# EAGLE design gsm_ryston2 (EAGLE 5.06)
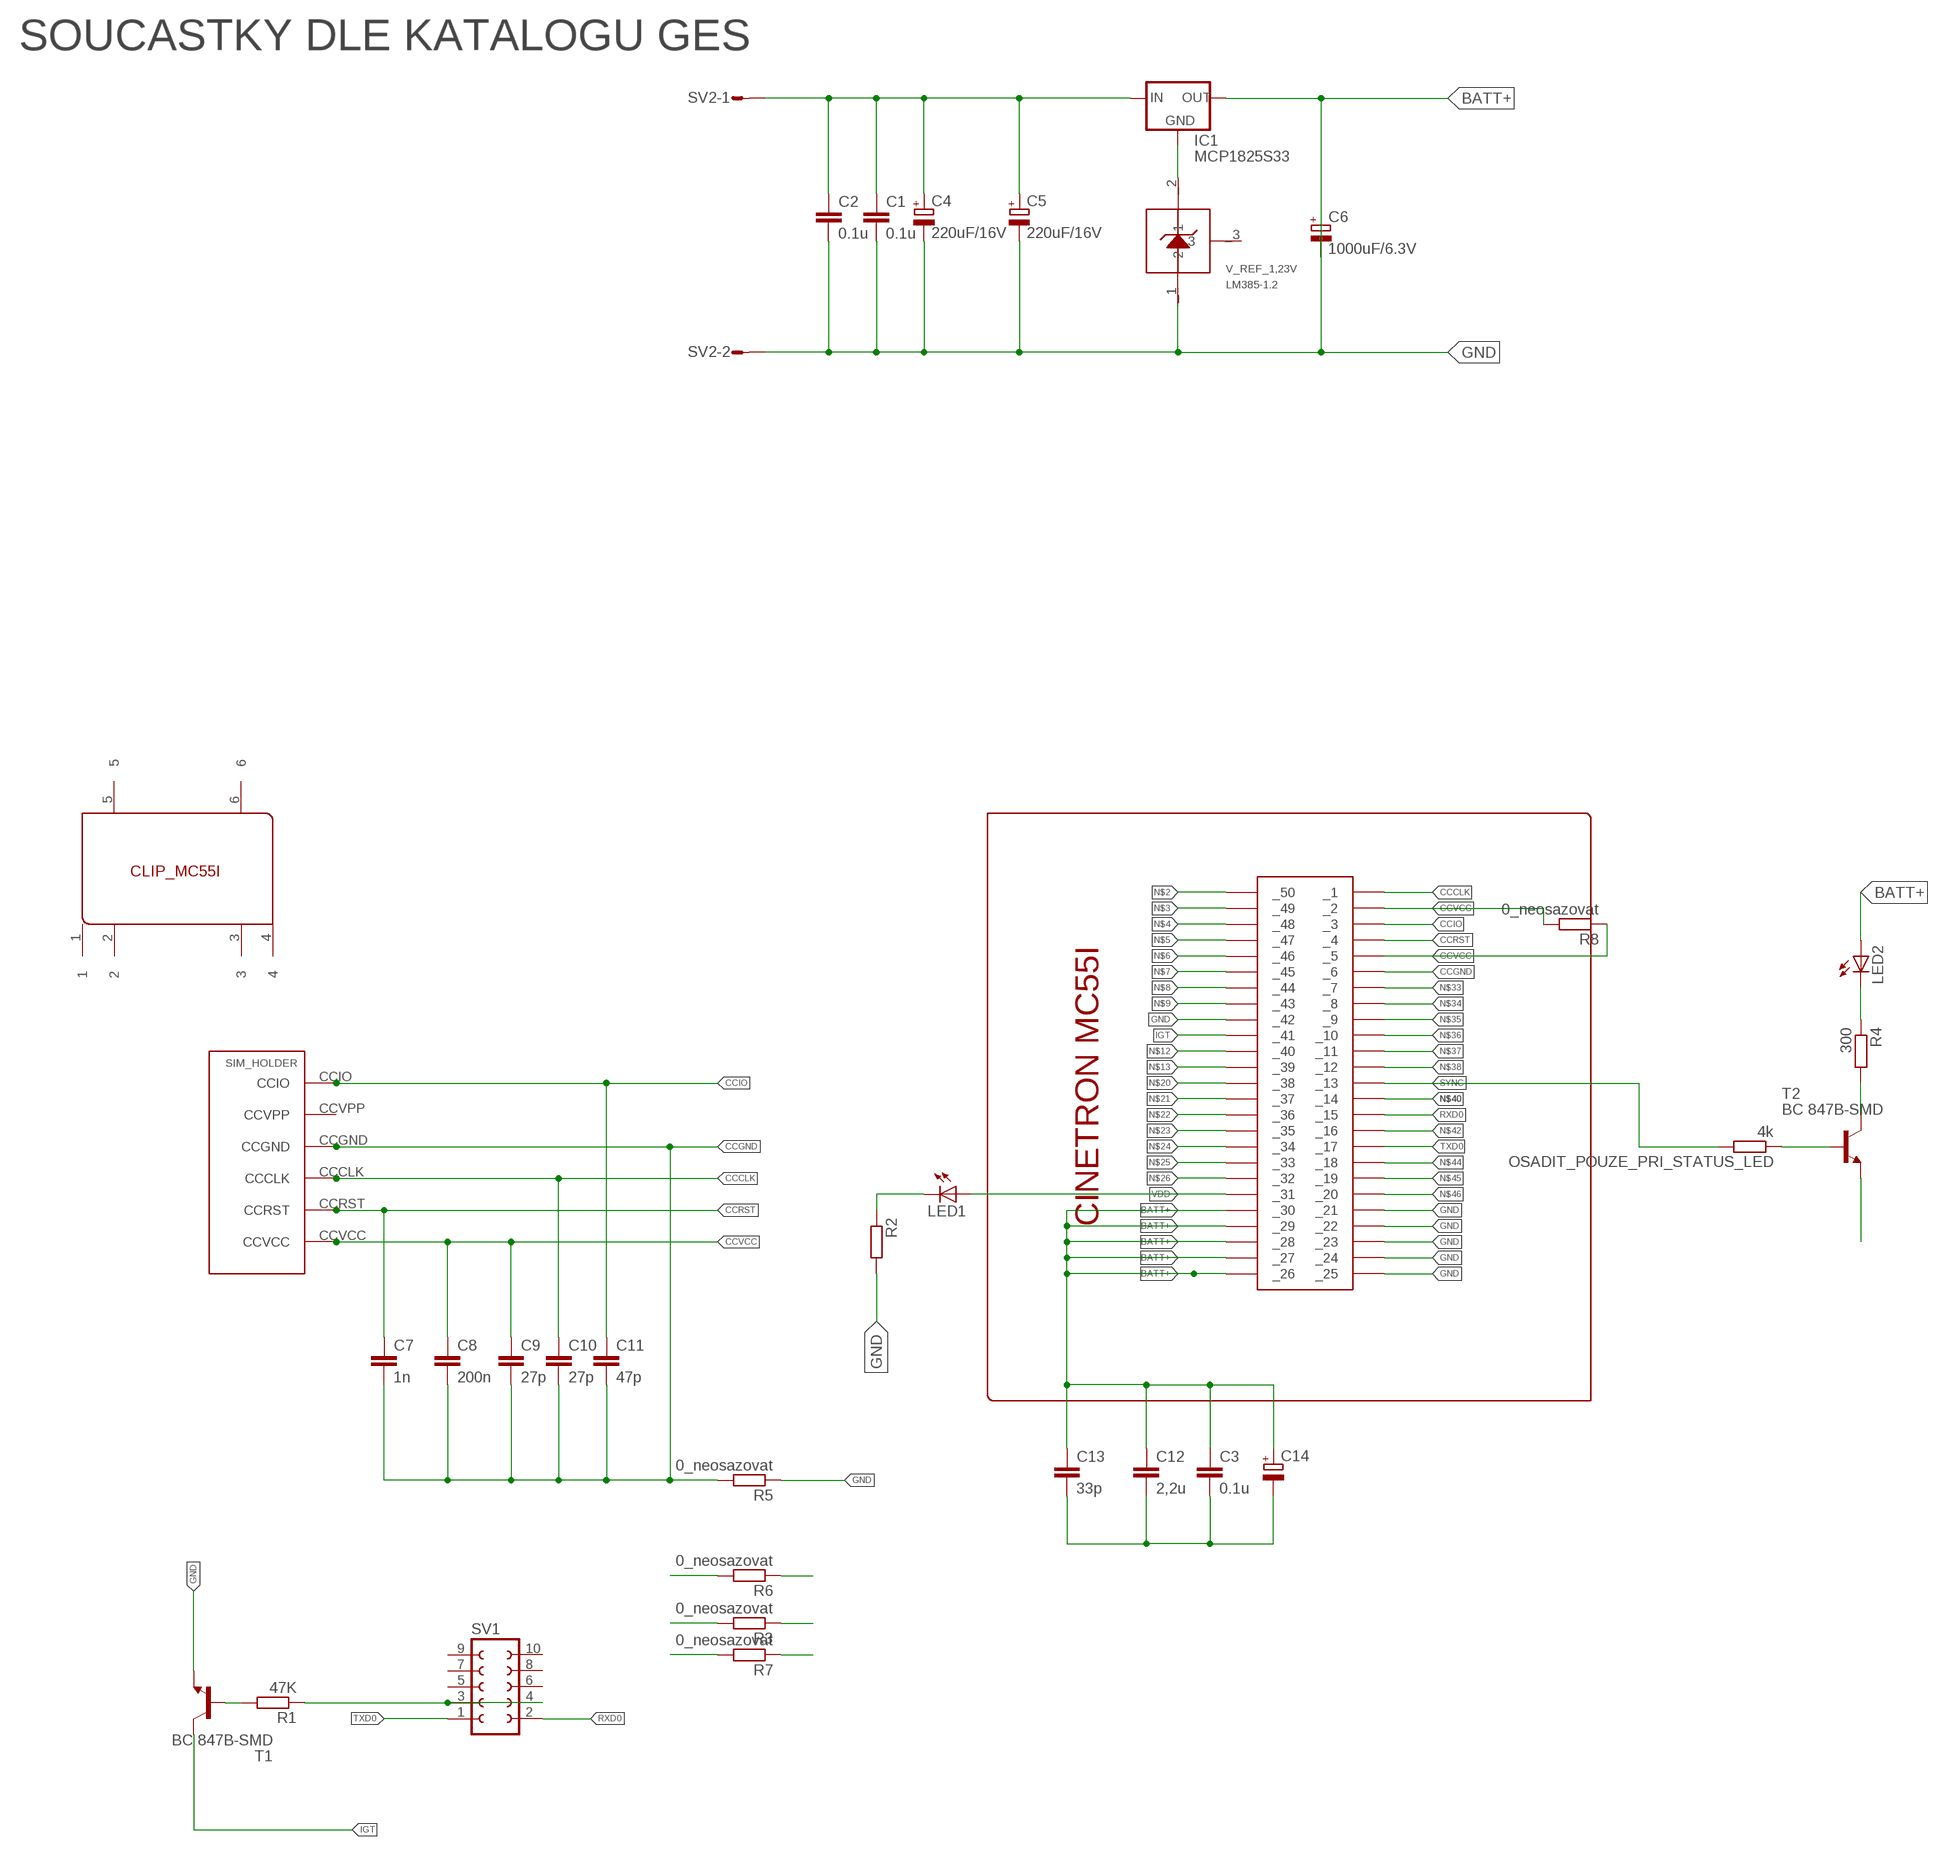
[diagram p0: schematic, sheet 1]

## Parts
C1  0.1u  C-EUC1206K  [C1206K]
C2  0.1u  C-EUC1206K  [C1206K]
C3  0.1u  C-EUC1206K  [C1206K]
C4  220uF/16V  CPOL-EUE2.5-6  [E2,5-6]
C5  220uF/16V  CPOL-EUE2.5-6  [E2,5-6]
C6  1000uF/6.3V  CPOL-EUF  [PANASONIC_F]
C7  1n  C-EUC1206K  [C1206K]
C8  200n  C-EUC1206K  [C1206K]
C9  27p  C-EUC1206K  [C1206K]
C10  27p  C-EUC1206K  [C1206K]
C11  47p  C-EUC1206K  [C1206K]
C12  2,2u  C-EUC1206K  [C1206K]
C13  33p  C-EUC1206K  [C1206K]
C14  CPOL-EUE2.5-6  [E2,5-6]
GND  CLIP_MC55I  [CLIP]
IC1  MCP1825S33  78XXL  [78XXL]
LED1  LEDCHIPLED_1206  [CHIPLED_1206]
LED2  LEDCHIPLED_1206  [CHIPLED_1206]
OSADIT_POUZE_PRI_STATUS_LED  4k  R-EU_M1206  [M1206]
R1  47K  R-EU_M1206  [M1206]
R2  R-EU_M1206  [M1206]
R3  0_neosazovat  R-EU_M1206  [M1206]
R4  300  R-EU_M1206  [M1206]
R5  0_neosazovat  R-EU_M1206  [M1206]
R6  0_neosazovat  R-EU_M1206  [M1206]
R7  0_neosazovat  R-EU_M1206  [M1206]
R8  0_neosazovat  R-EU_M1206  [M1206]
SIM_HOLDER  SIM_CINETRON_MC55I  [SIM_HOLDER]
SV1  FE05-2W  [FE05-2W]
SV2  L02P  [L02P]
T1  BC 847B-SMD  BC847  [SOT23]
T2  BC 847B-SMD  BC847  [SOT23]
U$2  CON  [CON]
V_REF_1,23V  LM385-1.2  [TO-92]

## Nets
5VDD: C1.1 C2.1 C4.+ C5.+ IC1.IN SV2.1
BATT+: C3.1 C6.+ C12.1 C13.1 C14.+ IC1.OUT LED2.A U$2.26(_26) U$2.27(_27) U$2.28(_28) U$2.29(_29) U$2.30(_30)
CCCLK: C10.1 SIM_HOLDER.CCCLK U$2.1(_1)
CCGND: C7.2 C8.2 C9.2 C10.2 C11.2 R5.2 SIM_HOLDER.CCGND T2.2(E) U$2.6(_6)
CCIO: C11.1 SIM_HOLDER.CCIO U$2.3(_3)
CCRST: C7.1 SIM_HOLDER.CCRST U$2.4(_4)
CCVCC: C8.1 C9.1 R8.1 R8.2 SIM_HOLDER.CCVCC U$2.2(_2) U$2.5(_5)
GND: C1.2 C2.2 C3.2 C4.- C5.- C6.- C12.2 C13.2 C14.- R2.2 R3.1 R3.2 R5.1 R6.1 R6.2 R7.1 R7.2 SV2.2 T1.2(E) U$2.21(_21) U$2.22(_22) U$2.23(_23) U$2.24(_24) U$2.42(_42) U$2._25 V_REF_1,23V._1
IGT: T1.3(C) U$2.41(_41)
N$1: IC1.GND V_REF_1,23V._2
N$2: U$2.50(_50)
N$3: U$2.49(_49)
N$4: U$2.48(_48)
N$5: U$2.47(_47)
N$6: U$2.46(_46)
N$7: U$2.45(_45)
N$8: U$2.44(_44)
N$9: U$2.43(_43)
N$10: LED1.C R2.1
N$11: OSADIT_POUZE_PRI_STATUS_LED.1 T2.1(B)
N$12: U$2.40(_40)
N$13: U$2.39(_39)
N$14: R1.2 T1.1(B)
N$15: R1.1 SV1.3 SV1.4
N$16: R4.2 T2.3(C)
N$17: LED2.C R4.1
N$20: U$2.38(_38)
N$21: U$2.37(_37)
N$22: U$2.36(_36)
N$23: U$2.35(_35)
N$24: U$2.34(_34)
N$25: U$2.33(_33)
N$26: U$2.32(_32)
N$33: U$2.7(_7)
N$34: U$2.8(_8)
N$35: U$2.9(_9)
N$36: U$2.10(_10)
N$37: U$2.11(_11)
N$38: U$2.12(_12)
N$40: U$2.14(_14)
N$42: U$2.16(_16)
N$44: U$2.18(_18)
N$45: U$2.19(_19)
N$46: U$2.20(_20)
RXD0: SV1.2 U$2.15(_15)
SYNC: OSADIT_POUZE_PRI_STATUS_LED.2 U$2.13(_13)
TXD0: SV1.1 U$2.17(_17)
VDD: LED1.A U$2.31(_31)
Unconnected: GND.1 GND.2 GND.3 GND.4 GND.5 GND.6 SV1.5 SV1.6 SV1.7 SV1.8 SV1.9 SV1.10 V_REF_1,23V._3

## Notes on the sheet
- SOUCASTKY DLE KATALOGU GES

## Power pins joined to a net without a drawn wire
CCVPP: SIM_HOLDER.CCVPP

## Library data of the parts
C1-C3 C7-C13 = rcl:C-EU: CAPACITOR, European symbol
C4-C6 C14 = rcl:CPOL-EU: POLARIZED CAPACITOR, European symbol
GND = clip_MC55I:CLIP_MC55I: clip pro MC55I
IC1 = v-reg:78XXL: VOLTAGE REGULATOR
LED1 LED2 = led:LED: LED
OSADIT_POUZE_PRI_STATUS_LED R1-R8 = rcl:R-EU_: RESISTOR, European symbol
SIM_HOLDER = sim_holder:SIM_CINETRON_MC55I: DRZAK SIM KARTY PRO MC55I
SV1 = con-lsta:FE05-2W: FEMALE HEADER
SV2 = con-amp-mt:L02P: AMP MT CONNECTOR
T1 T2 = transistor:BC847: NPN TRANSISTOR
U$2 = cinetron_MC55I :CON: Konektor pro GSM modul MC55i samicka (na BRD)
V_REF_1,23V = LM385-1.2:LM385-1.2: nampetova reference

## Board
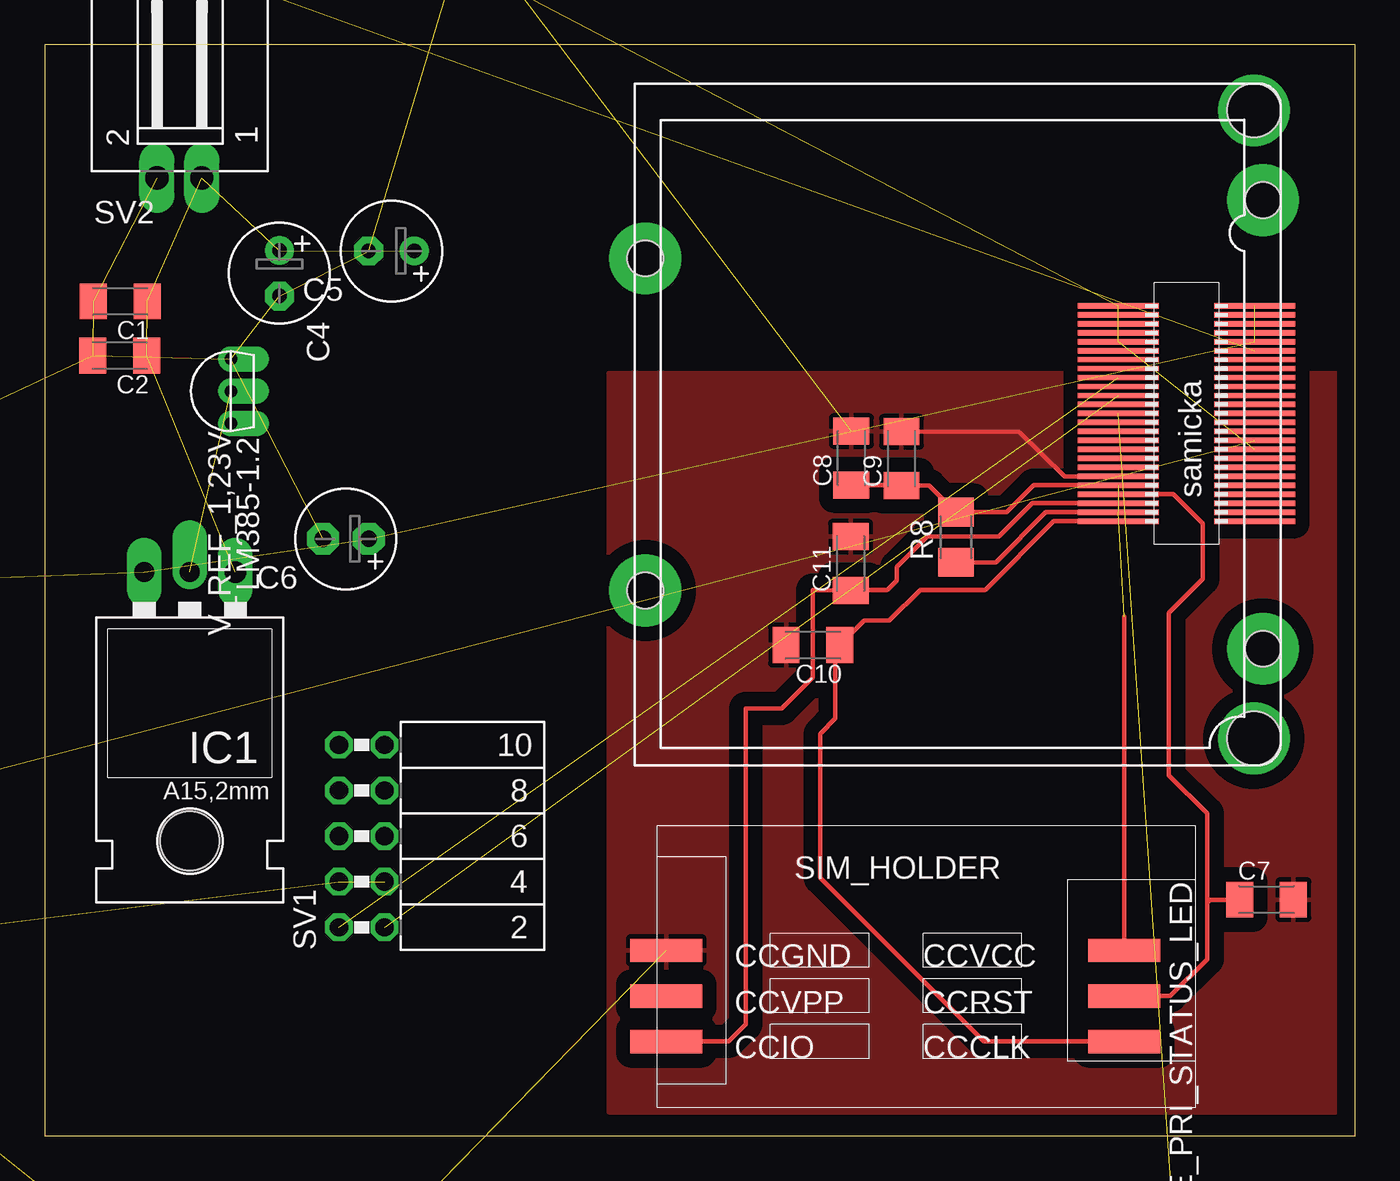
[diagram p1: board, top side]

Size 72.98 x 60.8 mm. Coordinates in mm from the lower left corner, seen from the top.
Outline: 0,0 72.98,0 72.98,60.8 0,60.8 0,0
Copper layers (1*16): Top 0.035mm / dielectric 1.5mm / Bottom 0.035mm
Design rules "default *": minimum track width 10mil, minimum drill 24mil, track to track 5mil, track to pad 5mil, pad to pad 5mil, via to via 5mil, smd to smd 5mil, copper to edge 40mil, drill to drill 8mil, minimum pad ring 10mil, minimum via ring 8mil, stop-mask expansion 4mil, vias tented up to drill 0mil, thermal gap 10mil

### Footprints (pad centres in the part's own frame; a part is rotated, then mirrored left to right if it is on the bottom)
C1206K = smd 1.5 x 2: 1 -1.5,0; 2 1.5,0
E2,5-6 = drill 0.813 pad 1.6 round: + -1.27,0 | drill 0.813 pad 1.6 octagon: - 1.27,0
E2,5-6@1 = drill 0.9 pad 1.778 octagon: + -1.27,0; - 1.27,0
CLIP = drill 2 pad 4 round: 1 0,0; 2 5,-0.5; 3 30,-0.5; 4 35,0; 5 8.25,33.9; 6 26.75,33.9 | hole 2: 8.25,33.9; 26.75,33.9; 5,-0.5; 30,-0.5 | hole 3: 0,0; 35,0
78XXL = drill 1.1 pad 1.93 offset: GND 0,-3.81 | drill 1.2 pad 1.93 long: IN -2.54,-3.81 | drill 1.1 pad 1.93 long: OUT 2.54,-3.81 | hole 3.302: 0,11.176
CHIPLED_1206 = smd 1.5 x 1.5: A 0,-1.75; C 0,1.75
M1206 = smd 1.6 x 2: 1 -1.4,0; 2 1.4,0
SIM_HOLDER = smd 4 x 1.3: CCCLK 26,3.65; CCGND 0.5,8.73; CCIO 0.5,3.65; CCRST 26,6.19; CCVCC 26,8.73; CCVPP 0.5,6.19
FE05-2W = drill 1.016 octagon: 1 -5.08,1.27; 2 -5.08,-1.27; 3 -2.54,1.27; 4 -2.54,-1.27; 5 0,1.27; 6 0,-1.27; 7 2.54,1.27; 8 2.54,-1.27; 9 5.08,1.27; 10 5.08,-1.27
L02P = drill 1.3 long: 1 1.25,-6.25; 2 -1.25,-6.25
SOT23 = smd 1 x 1.4: 1 -0.95,-1.1; 2 0.95,-1.1; 3 0,1.1
CON = smd 4.5 x 0.3: 1 3.8,6.05; 2 3.8,5.55; 3 3.8,5.05; 4 3.8,4.55; 5 3.8,4.05; 6 3.8,3.55; 7 3.8,3.05; 8 3.8,2.55; 9 3.8,2.05; 10 3.8,1.55; 11 3.8,1.05; 12 3.8,0.55; 13 3.8,0.05; 14 3.8,-0.45; 15 3.8,-0.95; 16 3.8,-1.45; 17 3.8,-1.95; 18 3.8,-2.45; 19 3.8,-2.95; 20 3.8,-3.45; 21 3.8,-3.95; 22 3.8,-4.45; 23 3.8,-4.95; 24 3.8,-5.45; 26 -3.8,-5.95; 27 -3.8,-5.45; 28 -3.8,-4.95; 29 -3.8,-4.45; 30 -3.8,-3.95; 31 -3.8,-3.45; 32 -3.8,-2.95; 33 -3.8,-2.45; 34 -3.8,-1.95; 35 -3.8,-1.45; 36 -3.8,-0.95; 37 -3.8,-0.45; 38 -3.8,0.05; 39 -3.8,0.55; 40 -3.8,1.05; 41 -3.8,1.55; 42 -3.8,2.05; 43 -3.8,2.55; 44 -3.8,3.55; 45 -3.8,3.05; 46 -3.8,4.05; 47 -3.8,4.55; 48 -3.8,5.05; 49 -3.8,5.55; 50 -3.8,6.05; _25 3.8,-5.95
TO-92 = drill 0.7 pad 1.422 offset: _1 -1.8,0; _2 0,0; _3 1.8,0

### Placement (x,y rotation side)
C1  4.2,46.51 180 top
C2  4.18,43.48 180 top
C3  not placed on the board
C4  13.07,48.07 270 top
C5  19.3,49.31 180 top
C6  1000uF/6.3V  [E2,5-6@1]  16.76,33.28 180 top
C7  68.04,13.17 0 top
C8  44.92,37.78 90 top
C9  47.71,37.74 90 top
C10  42.78,27.36 180 top
C11  44.88,31.9 90 top
C12  not placed on the board
C13  not placed on the board
C14  not placed on the board
GND  67.34,22.15 90 top
IC1  8.07,27.61 180 top
LED1  not placed on the board
LED2  not placed on the board
OSADIT_POUZE_PRI_STATUS_LED  not placed on the board
R1  not placed on the board
R2  not placed on the board
R3  not placed on the board
R4  not placed on the board
R5  not placed on the board
R6  not placed on the board
R7  not placed on the board
R8  50.75,33.36 90 top
SIM_HOLDER  34.11,1.61 0 top
SV1  17.65,16.71 90 top
SV2  7.49,59.63 0 top
T1  not placed on the board
T2  not placed on the board
U$2  63.59,40.31 180 top
V_REF_1,23V  10.36,41.5 270 top

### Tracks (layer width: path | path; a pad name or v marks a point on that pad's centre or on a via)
5VDD  (5 unrouted)
BATT+  (11 unrouted)
CCCLK
  Top 0.254: SIM_HOLDER.CCCLK 52.3,5.26 43.18,14.39 43.18,22.4 44.03,23.25 44.03,24.31 44.03,27.11 C10.1 45.64,28.71 47.04,28.71 48.75,30.43 52.37,30.43 56.2,34.26 U$2.1
CCGND  (2 unrouted)
  Top 0.254: C9.2 54.28,39.23 56.79,36.75 U$2.6
  pour Top (isolate 0.813): 31.4,1.33 31.4,42.52 72.45,42.52 72.45,1.33
CCIO
  Top 0.254: SIM_HOLDER.CCIO 38.1,5.26 39.05,6.21 39.05,23.83 41.04,23.83 42.78,25.56 42.78,30.42 C11.1 44.9,30.42 46.92,30.42 47.46,30.95 47.46,31.7 49.16,33.4 53.13,33.4 54.99,35.26 U$2.3
CCRST
  Top 0.254: 62.36,7.8 SIM_HOLDER.CCRST 62.69,7.8 64.73,9.84 64.73,12.98 | 64.73,12.98 64.73,17.97 62.61,20.09 62.61,29.15 64.49,31.03 64.49,34.12 62.85,35.76 U$2.4 | C7.1 64.92,13.17 64.73,12.98
CCVCC  (2 unrouted)
  Top 0.254: U$2.2 55.75,34.76 52.96,31.97 R8.1 | SIM_HOLDER.CCVCC 60.11,28.96 | C8.1 47.67,36.28 C9.1 49.27,36.24 R8.2 53.57,34.76 55,36.19 55.07,36.26 U$2.5
GND  (25 unrouted)
IGT  (1 unrouted)
N$1  (1 unrouted)
N$10  (1 unrouted)
N$11  (1 unrouted)
N$14  (1 unrouted)
N$15  (2 unrouted)
N$16  (1 unrouted)
N$17  (1 unrouted)
RXD0  (1 unrouted)
SYNC  (1 unrouted)
TXD0  (1 unrouted)
VDD  (1 unrouted)

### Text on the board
Top: GSM_modul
